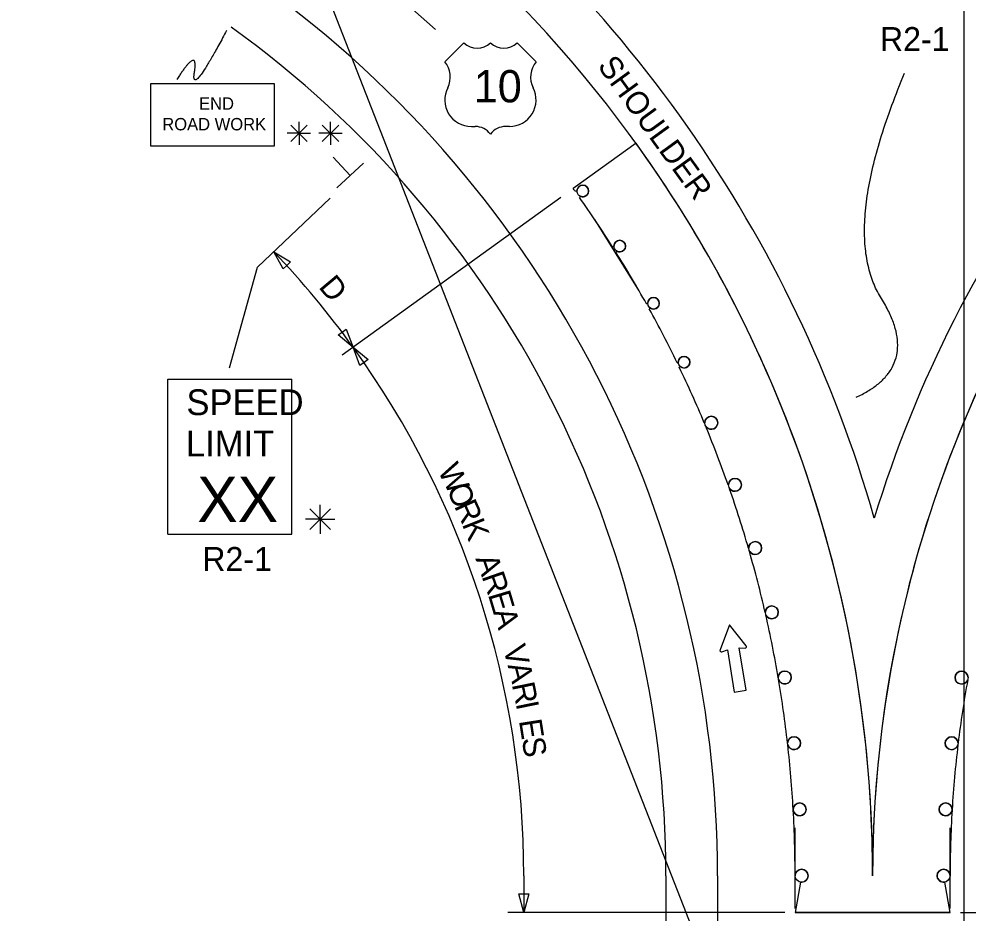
# Model space of a CAD drawing. Extents: x 16486 to 19505, y 5576 to 6998.
# Drawn here: x 16688.1 to 16981.9, y 6469 to 6745.9 of the extents above; entities that cross this region are included whole.
import ezdxf

# ---------------------------------------------------------------- set-up
doc = ezdxf.new("R2010")
doc.units = 0
for name, color, linetype in [('ALI_LEGAL_EX', 7, 'Continuous'), ('MT_SCRATCH_LEVEL_A', 7, 'Continuous'), ('MT_SCRATCH_LEVEL_E', 7, 'Continuous'), ('PAVT_EDGE_EX', 7, 'Continuous'), ('TRAFFIC_SIGNS_PR', 7, 'Continuous'), ('TYPICAL_EX', 7, 'Continuous'), ('TYPICAL_TEXT_DIMEN_PR', 7, 'Continuous')]:
    doc.layers.add(name, color=color, linetype=linetype)

msp = doc.modelspace()

# ---------------------------------------------------------------- linework, layer by layer
at = {"layer": 'ALI_LEGAL_EX'}
for p, q in [((16688.08, 6997.81), (16910.11, 6429.44)), ((16980.68, 6974.12), (16980.68, 6155.98)), ((16980.68, 6922.21), (16980.68, 6058.3))]:
    msp.add_line(p, q, dxfattribs=at)
for points in [[(16817.07, 6742.72), (16798.4, 6759.35)], [(16879.58, 6662.6), (16866.35, 6683.82)], [(16879.58, 6662.6), (16866.35, 6683.82)], [(16928.4, 6470.33), (16928.4, 6495.33)], [(16976.4, 6470.33), (16976.4, 6495.33)]]:
    msp.add_lwpolyline(points, dxfattribs=at)
at = {"layer": 'MT_SCRATCH_LEVEL_A'}
for p, q in [((16976.4, 6469.09), (16928.4, 6469.09)), ((16928.4, 6469.09), (16976.4, 6469.09)), ((16976.4, 6469.09), (16928.4, 6469.09)), ((16976.19, 6469.09), (16976.4, 6469.3))]:
    msp.add_line(p, q, dxfattribs=at)
for points in [[(16879.14, 6707.43), (16859.67, 6693.39)], [(16860.17, 6692.7), (16860.85, 6692.69)], [(16862.05, 6690.97), (16861.62, 6690.66)], [(16871.89, 6675.32), (16872.3, 6675.58)], [(16873.31, 6673.96), (16872.91, 6673.71)], [(16882.39, 6657.67), (16882.76, 6657.87)], [(16883.6, 6656.35), (16883.23, 6656.15)], [(16891.88, 6639.44), (16892.22, 6639.61)], [(16892.9, 6638.2), (16892.56, 6638.04)], [(16900.29, 6620.78), (16900.44, 6620.85)], [(16901.02, 6619.44), (16900.88, 6619.38)], [(16907.68, 6601.59), (16907.79, 6601.63)], [(16908.22, 6600.39), (16908.11, 6600.35)], [(16913.97, 6582.02), (16914.05, 6582.04)], [(16914.35, 6580.98), (16914.27, 6580.96)], [(16919.14, 6562.11), (16919.19, 6562.12)], [(16919.39, 6561.26), (16919.34, 6561.25)], [(16923.18, 6541.95), (16923.21, 6541.95)], [(16923.33, 6541.3), (16923.29, 6541.29)], [(16981.86, 6541.2), (16981.82, 6541.21)], [(16926.08, 6521.59), (16926.1, 6521.59)], [(16926.14, 6521.14), (16926.13, 6521.14)], [(16978.83, 6521.1), (16978.81, 6521.1)], [(16978.87, 6521.57), (16978.89, 6521.57)], [(16927.82, 6501.09), (16927.83, 6501.09)], [(16927.84, 6500.87), (16927.83, 6500.87)], [(16977.01, 6500.85), (16977, 6500.85)], [(16977.01, 6501.09), (16977.02, 6501.09)], [(16928.4, 6480.53), (16928.41, 6480.53)], [(16976.39, 6480.53), (16976.4, 6480.53)], [(16930.06, 6478.56), (16928.4, 6469.09), (16976.4, 6469.09), (16974.74, 6478.56)]]:
    msp.add_lwpolyline(points, dxfattribs=at)
for centre, radius, start, end in [((16564.4, 6480.53), 388, 22.8554, 35.7873), ((17316.4, 6480.53), 364, 141.7598, 180), ((16862.65, 6692.67), 1.8, 0, 179.0978), ((16564.4, 6480.53), 364, 35.6537, 35.7873), ((16862.65, 6692.67), 1.8, 250.5205, 0), ((16564.4, 6480.53), 364, 32.3536, 35.2603), ((16874.1, 6675.58), 1.8, 0, 180), ((16874.1, 6675.58), 1.8, 244.1065, 0), ((16564.4, 6480.53), 364, 29.1198, 32.0533), ((16884.56, 6657.87), 1.8, 0, 180), ((16884.56, 6657.87), 1.8, 237.6934, 0), ((16564.4, 6480.53), 364, 25.8855, 28.8467), ((16894.02, 6639.61), 1.8, 0, 180), ((16894.02, 6639.61), 1.8, 231.2811, 0), ((16564.4, 6480.53), 364, 22.663, 25.6406), ((16564.4, 6480.53), 388, 0, 22.8554), ((16564.4, 6480.53), 388, 0, 22.8554), ((16564.4, 6480.53), 388, 0, 22.8554), ((16902.44, 6620.85), 2, 0, 180), ((16564.4, 6480.53), 364, 19.4261, 22.4229), ((16902.44, 6620.85), 2, 224.8459, 0), ((16909.79, 6601.63), 2, 0, 180), ((16909.79, 6601.63), 2, 218.4379, 0), ((16564.4, 6480.53), 364, 16.189, 19.219), ((16916.05, 6582.04), 2, 0, 180), ((16564.4, 6480.53), 364, 12.9515, 16.0153), ((16916.05, 6582.04), 2, 212.0306, 0), ((16921.19, 6562.13), 2, 0, 180), ((16564.4, 6480.53), 364, 9.7138, 12.8119), ((16921.19, 6562.13), 2, 205.6238, 0), ((16925.21, 6541.95), 2, 0, 180), ((16925.21, 6541.95), 2, 199.2175, 0), ((16979.95, 6541.91), 2, 0, 180), ((16979.95, 6541.91), 2, 180, 339.4418), ((16564.4, 6480.53), 364, 6.476, 9.6087), ((17316.4, 6480.53), 340, 169.7209, 173.067), ((16928.09, 6521.59), 2, 0, 180), ((16564.4, 6480.53), 364, 3.238, 6.4057), ((16928.09, 6521.59), 2, 192.8115, 0), ((16976.87, 6521.57), 2, 0, 180), ((16976.87, 6521.57), 2, 180, 346.2947), ((17316.4, 6480.53), 340, 173.1474, 176.5334), ((16929.83, 6501.09), 2, 0, 180), ((16564.4, 6480.53), 364, 0, 3.2028), ((16929.83, 6501.09), 2, 186.4057, 0), ((16975.01, 6501.09), 2, 0, 180), ((16975.01, 6501.09), 2, 180, 353.1474), ((17316.4, 6480.53), 340, 176.5737, 180), ((16930.41, 6480.53), 2, 0, 180), ((16930.41, 6480.53), 2, 260.0595, 0), ((16974.39, 6480.53), 2, 0, 180), ((16974.39, 6480.53), 2, 180, 279.941)]:
    msp.add_arc(centre, radius, start, end, dxfattribs=at)
at = {"layer": 'MT_SCRATCH_LEVEL_E'}
for p, q in [((16908.07, 6558.3), (16905.15, 6550.5)), ((16913.3, 6551.8), (16908.07, 6558.3)), ((16905.73, 6549.9), (16907.44, 6550.49)), ((16907.44, 6550.49), (16909.52, 6537.4)), ((16913.22, 6537.99), (16911.13, 6551.08)), ((16911.13, 6551.08), (16912.94, 6551.05)), ((16909.52, 6537.4), (16913.22, 6537.99))]:
    msp.add_line(p, q, dxfattribs=at)
for centre, start, end in [((16905.59, 6550.34), 159.4773, 289.0163), ((16912.93, 6551.51), 269.0886, 38.8256)]:
    msp.add_arc(centre, 0.463, start, end, dxfattribs=at)
at = {"layer": 'PAVT_EDGE_EX'}
for p, q in [((16888.4, 6480.53), (16888.4, 6125.9)), ((16904.4, 6480.53), (16904.4, 6125.9))]:
    msp.add_line(p, q, dxfattribs=at)
for centre, radius, start, end in [((16564.4, 6480.53), 404, 15.917, 54.2283), ((17316.4, 6480.53), 380, 123.1879, 163.0483), ((16564.4, 6480.53), 388, 0, 54.2283), ((17316.4, 6480.53), 364, 123.1879, 180), ((16564.4, 6480.53), 340, 0, 54.2283), ((16564.4, 6480.53), 324, 0, 54.2283)]:
    msp.add_arc(centre, radius, start, end, dxfattribs=at)
at = {"layer": 'TRAFFIC_SIGNS_PR'}
for p, q in [((16734.17, 6634.36), (16772.57, 6634.36)), ((16734.17, 6586.36), (16734.17, 6634.36)), ((16772.57, 6586.36), (16772.57, 6634.36)), ((16734.17, 6586.36), (16772.57, 6586.36))]:
    msp.add_line(p, q, dxfattribs=at)
msp.add_lwpolyline([(16728.84, 6706.69), (16767.24, 6706.69), (16767.24, 6725.89), (16728.84, 6725.89)], close=True, dxfattribs=at)
for centre, radius in [((16862.65, 6692.67), 1.8), ((16874.1, 6675.58), 1.8), ((16884.56, 6657.87), 1.8), ((16894.02, 6639.61), 1.8), ((16902.44, 6620.85), 2), ((16909.79, 6601.63), 2), ((16916.05, 6582.04), 2), ((16921.19, 6562.13), 2), ((16925.21, 6541.95), 2), ((16979.95, 6541.91), 2), ((16928.09, 6521.59), 2), ((16976.87, 6521.57), 2), ((16929.83, 6501.09), 2), ((16975.01, 6501.09), 2), ((16930.41, 6480.53), 2), ((16974.39, 6480.53), 2)]:
    msp.add_circle(centre, radius, dxfattribs=at)
at = {"layer": 'TYPICAL_EX'}
for p, q in [((16819.91, 6732.69), (16825.81, 6738.58)), ((16848.21, 6732.69), (16842.31, 6738.58)), ((16828.16, 6712.63), (16829.33, 6712.63)), ((16839.96, 6712.63), (16838.78, 6712.63))]:
    msp.add_line(p, q, dxfattribs=at)
for centre, radius, start, end in [((16829.93, 6742.88), 5.96, 226.1404, 313.8596), ((16838.19, 6742.88), 5.96, 226.1404, 313.8596), ((16814.32, 6727.97), 7.31, 333.0977, 40.1936), ((16853.8, 6727.97), 7.31, 139.8064, 206.9023), ((16828.17, 6720.87), 8.24, 152.6698, 269.9013), ((16839.95, 6720.87), 8.24, 270.0987, 27.3302), ((16829.35, 6706.72), 5.91, 37.1038, 90.1385), ((16838.77, 6706.72), 5.91, 89.8615, 142.8962)]:
    msp.add_arc(centre, radius, start, end, dxfattribs=at)
at = {"layer": 'TYPICAL_TEXT_DIMEN_PR'}
for p, q in [((16772.24, 6713.07), (16777.34, 6707.96)), ((16777.34, 6713.07), (16772.24, 6707.96)), ((16774.79, 6710.52), (16774.79, 6714.08)), ((16781.99, 6713.07), (16787.09, 6707.96)), ((16787.09, 6713.07), (16781.99, 6707.96)), ((16784.54, 6710.52), (16784.54, 6714.08)), ((16774.79, 6710.52), (16771.17, 6710.52)), ((16774.79, 6710.52), (16777.34, 6710.52)), ((16774.79, 6710.52), (16778.38, 6710.52)), ((16774.79, 6710.52), (16774.79, 6706.91)), ((16784.54, 6710.52), (16780.91, 6710.52)), ((16784.54, 6710.52), (16787.09, 6710.52)), ((16784.54, 6710.52), (16788.12, 6710.52)), ((16784.54, 6710.52), (16784.54, 6706.91)), ((16790.63, 6697.41), (16785.35, 6703.13)), ((16794.76, 6701.23), (16786.5, 6693.59)), ((16784.43, 6690.48), (16761.94, 6669.02)), ((16855.89, 6690.66), (16788.1, 6641.79)), ((16769.88, 6668.5), (16766.97, 6673.83)), ((16766.97, 6673.83), (16772.16, 6670.67)), ((16753.24, 6637.84), (16761.94, 6669.02)), ((16771.02, 6669.59), (16769.88, 6668.5)), ((16772.16, 6670.67), (16771.02, 6669.59)), ((16786.88, 6648.05), (16788.15, 6648.96)), ((16791.58, 6644.21), (16786.88, 6648.05)), ((16788.15, 6648.96), (16789.43, 6649.88)), ((16789.43, 6649.88), (16791.58, 6644.21)), ((16793.67, 6638.58), (16791.52, 6644.26)), ((16791.52, 6644.26), (16796.22, 6640.42)), ((16794.95, 6639.5), (16793.67, 6638.58)), ((16796.22, 6640.42), (16794.95, 6639.5)), ((16781.35, 6590.97), (16781.35, 6595.43)), ((16778.17, 6594.16), (16784.54, 6587.78)), ((16784.54, 6594.16), (16778.17, 6587.78)), ((16781.35, 6590.97), (16776.82, 6590.97)), ((16781.35, 6590.97), (16784.54, 6590.97)), ((16781.35, 6590.97), (16785.83, 6590.97)), ((16781.35, 6590.97), (16781.35, 6586.47)), ((16844.4, 6480.53), (16844.4, 6469.09)), ((16844.4, 6469.09), (16842.83, 6474.95)), ((16842.83, 6474.95), (16844.4, 6474.95)), ((16844.4, 6474.95), (16845.97, 6474.95)), ((16845.97, 6474.95), (16844.4, 6469.09)), ((16925.27, 6469.09), (16839.4, 6469.09)), ((16979.6, 6469.09), (17065.4, 6469.09))]:
    msp.add_line(p, q, dxfattribs=at)
for start, end in [(35.772, 43.6576), (0, 35.7873)]:
    msp.add_arc((16564.4, 6480.53), 280, start, end, dxfattribs=at)
for points in [[(16752.36, 6742.34), (16741.04, 6721.04), (16743.78, 6737.81), (16736.96, 6727.21)], [(16947.29, 6628.75), (16968.28, 6638.37), (16941.9, 6680.45), (16962.28, 6729.14)]]:
    msp.add_open_spline(points, degree=2, dxfattribs=at)

# ---------------------------------------------------------------- texts
at = {"layer": 'TRAFFIC_SIGNS_PR'}
for s, height, p in [('R2-1', 7.44, (16954.67, 6735.99)), ('END', 3.831, (16743.84, 6717.82)), ('ROAD WORK', 3.831, (16732.45, 6711.44)), ('SPEED', 8, (16739.93, 6623.22)), ('LIMIT', 8, (16739.77, 6610.42)), ('XX', 14.031, (16743.28, 6590.11)), ('R2-1', 7.44, (16744.84, 6574.92))]:
    msp.add_text(s, height=height, dxfattribs=at).set_placement(p)
at = {"layer": 'TYPICAL_EX'}
msp.add_text('10', height=10, dxfattribs=at).set_placement((16828.9, 6720.11))
at = {"layer": 'TYPICAL_TEXT_DIMEN_PR'}
for s, rotation, p in [('SHOULDER', 305.9489, (16867.02, 6731.38)), ('D', 310, (16780.62, 6662.86)), ('W', 296.9052, (16817.6, 6606.11)), ('O', 294.3428, (16820.37, 6600.33)), ('R', 294.3428, (16822.74, 6595.07)), ('K', 291.7804, (16825.16, 6589.46)), ('A', 289.218, (16829.38, 6578.75)), ('R', 289.218, (16831.27, 6573.31)), ('E', 286.6556, (16833.24, 6567.65)), ('A', 286.6556, (16834.83, 6562.33)), ('V', 284.0932, (16837.97, 6551.14)), ('A', 284.0932, (16839.33, 6545.74)), ('R', 281.5308, (16840.66, 6539.81)), ('I', 281.5308, (16841.87, 6533.92)), ('E', 278.9684, (16842.87, 6528.58)), ('S', 278.9684, (16843.75, 6522.99))]:
    msp.add_text(s, height=7, rotation=rotation, dxfattribs=at).set_placement(p)

doc.saveas('drawing.dxf')
